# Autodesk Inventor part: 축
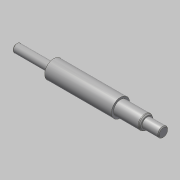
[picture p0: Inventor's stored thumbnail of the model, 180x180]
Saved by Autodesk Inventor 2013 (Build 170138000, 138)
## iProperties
Created: 2016-05
Part Number: 축
Document SubType Name: Modeling
Designer: mduedu
Density: 7.86 g/cm^3
Material: 강철, 연강
Author: mduedu
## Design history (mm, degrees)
sketch "스케치1"
  geometry: L1 (-44, 11)-(-44, 5); L2 (37, 11)-(37, 8.5); L3 (-89, 0)-(89, 0); L4 (-44, 11)-(37, 11); L5 (37, 11)-(37, 8.5); L6 (-44, 11)-(-44, 5); L7 (-44, 5)-(-89, 5); L8 (-89, 5)-(-89, 0); L9 (37, 8.5)-(69, 8.5); L10 (89, 6)-(89, 0); L11 (69, 8.5)-(69, 6); L12 (69, 6)-(89, 6); 1 further point
  constraints: 24 end point, 9 perpendicular, 2 midpoint, 1 horizontal
  dimensions: "d0" = 22 diameter of L4 L3; "d1" = 10 diameter of L7 L3; "d2" = 45 distance between parallel lines of L8 L1; "d3" = 52 distance between parallel lines of L10 L2; "d4" = 12 diameter of L12 L3; "d5" = 20 distance between parallel lines of L10 L11; "d29" = 81 distance of L1.start L2.start; "d37" = 17 diameter of L9 L3
revolve "회전1" stored, may be unused: angle "d6" = 90 deg
chamfer "모따기2" distance "d32" = 1; stored, may be unused: second distance "d33" = 2, angle "d34" = 45 deg
node "작업 평면4"
sketch "스케치4"
  geometry: L1 (-5, 2)-(5, 2); L2 (5, -2)-(-5, -2); L3 (-10, -5)-(-10, 5) reference; A1 r 2 centre (5, 0) between (5, -2) and (5, 2); A2 r 2 centre (-5, 0) between (-5, 2) and (-5, -2); 1 further point
  constraints: 4 end point, 4 point on circle, 4 tangent, 2 centre point, 1 horizontal, 1 horizontal alignment, 1 parallel
  dimensions: "d20" = 4 distance between parallel lines of L2 L1; "d21" = 14 dimension on A1 A2; "d35" = 3 distance edge to line of A2 L3
extrude "돌출3" cut sketch "스케치4" distance "d23" = 2.5; taper "d24" = 0 deg
node "작업 평면5"
sketch "스케치5"
  geometry: L1 (22.5, 1.5)-(12, 1.5); L2 (12, -1.5)-(22.5, -1.5); L3 (22.5, 4)-(22.5, -4) reference; A1 r 1.5 centre (12, 0) between (12, 1.5) and (12, -1.5); 3 further points
  constraints: 4 end point, 2 horizontal alignment, 2 point on circle, 2 point on line, 2 tangent, 1 centre point, 1 coincident, 1 horizontal, 1 midpoint
  dimensions: "d25" = 3 distance between parallel lines of L2 L1; "d36" = 12 dimension on A1 L3
extrude "돌출4" cut sketch "스케치5" distance "d27" = 1.8; taper "d28" = 0 deg
chamfer "모따기3" distance "d38" = 1.82; stored, may be unused: second distance "d39" = 2, angle "d40" = 30 deg
fillet "모깎기1" dims "d41" = 2
node "솔리드1"
